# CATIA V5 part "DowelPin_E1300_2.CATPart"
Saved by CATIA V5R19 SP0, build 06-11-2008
Part number: DowelPin_E1300_2
Nomenclature: E 1300/4x12
Source: Unknown
Description: MEUSBURGER
Bounding box of the stored display mesh (mm): x -1.996 to 1.996, y -2 to 2, z -6 to 6
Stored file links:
  C:\Users\jsmid\Desktop\DP_Smidak_Forma LEGO\DowelPin_E1300_2.CATPart
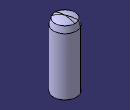
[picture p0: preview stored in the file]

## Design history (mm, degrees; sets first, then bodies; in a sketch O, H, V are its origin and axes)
Body1 (main body)
  Solid1 "PartBody": solid without history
